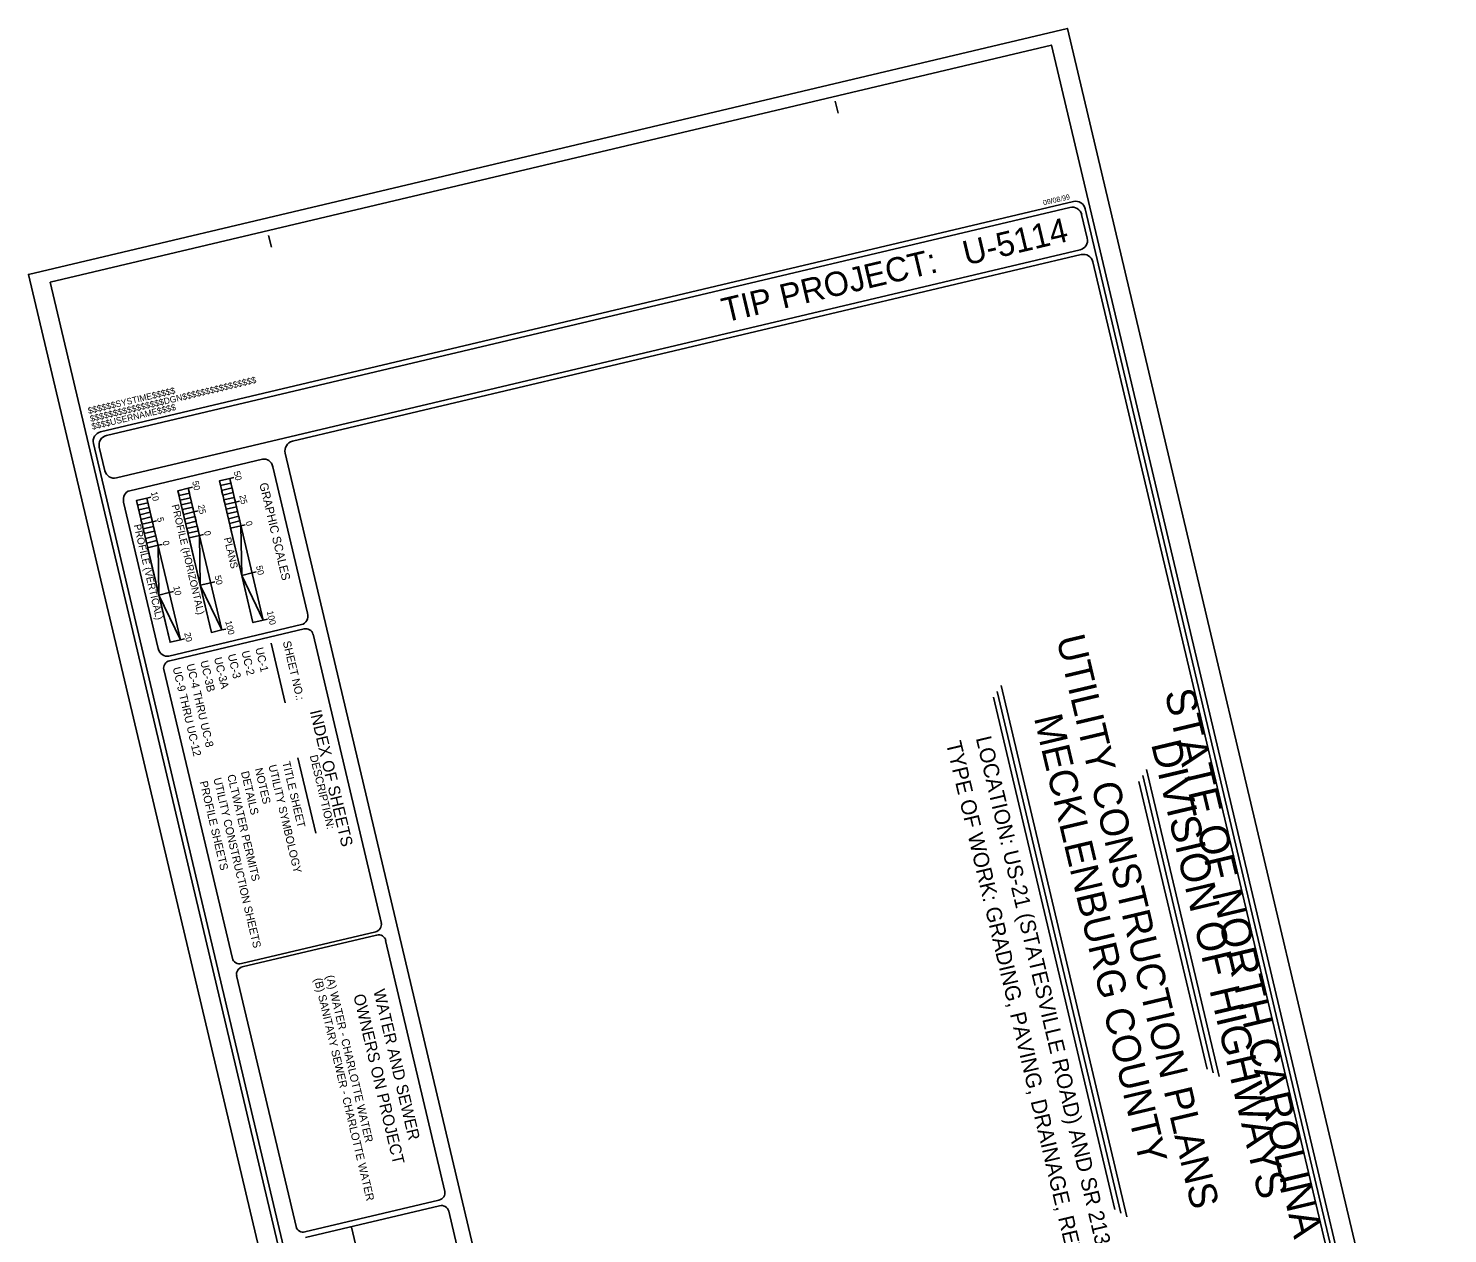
# Model space of a CAD drawing. Extents: x 1439200 to 1642353, y 394562 to 606444.
# Drawn here: x 1439200 to 1445633, y 600981 to 606444 of the extents above; entities that cross this region are included whole.
import ezdxf

# ---------------------------------------------------------------- set-up
doc = ezdxf.new("R2010")
doc.units = 0
doc.layers.add('Level 43', color=7, linetype='Continuous')
doc.layers.add('Water Line Text and Text Box and Leader Line (St)', color=7, linetype='Continuous')

msp = doc.modelspace()

# ---------------------------------------------------------------- linework, layer by layer
at = {"layer": 'Level 43'}
for p, q in [((1442857.6, 606113.3), (1442870.3, 606059.8)), ((1442857.6, 606113.3), (1442870.3, 606059.8)), ((1440288.6, 605505.1), (1440301.3, 605451.6)), ((1440288.6, 605505.1), (1440301.3, 605451.6)), ((1439599.3, 604406), (1443966.6, 605439.8)), ((1440396.5, 604572.1), (1443971.7, 605418.4)), ((1439484.4, 604604.9), (1439484.4, 604604.9)), ((1439484.4, 604604.9), (1439484.4, 604604.9)), ((1439484.4, 604604.9), (1439484.4, 604604.9)), ((1439484.4, 604604.9), (1439484.4, 604604.9)), ((1440363.8, 604519.2), (1441803.1, 598439.2)), ((1439659.1, 604348.4), (1440260.6, 604490.8)), ((1440308.3, 604456.9), (1440465.4, 603793.2)), ((1440112.9, 604403.8), (1440065.9, 604392.7)), ((1440065.9, 604392.7), (1440217.9, 603750.4)), ((1440112.9, 604403.8), (1440131.6, 604408.3)), ((1440112.9, 604403.8), (1440112.9, 604403.8)), ((1440264.9, 603761.6), (1440112.9, 604403.8)), ((1440131.6, 604408.3), (1440131.6, 604408.3)), ((1439736.9, 604314.8), (1439689.9, 604303.7)), ((1439689.9, 604303.7), (1439842, 603661.4)), ((1439736.9, 604314.8), (1439755.7, 604319.3)), ((1439736.9, 604314.8), (1439755.7, 604319.3)), ((1439736.9, 604314.8), (1439755.7, 604319.3)), ((1439736.9, 604314.8), (1439736.9, 604314.8)), ((1439889, 603672.6), (1439736.9, 604314.8)), ((1439736.9, 604314.8), (1439736.9, 604314.8)), ((1439889, 603672.6), (1439736.9, 604314.8)), ((1439736.9, 604314.8), (1439736.9, 604314.8)), ((1439889, 603672.6), (1439736.9, 604314.8)), ((1439755.7, 604319.3), (1439755.7, 604319.3)), ((1439924.8, 604359.3), (1439877.9, 604348.2)), ((1439877.9, 604348.2), (1440029.9, 603705.9)), ((1439924.8, 604359.3), (1439943.7, 604363.8)), ((1439924.8, 604359.3), (1439943.7, 604363.8)), ((1439924.8, 604359.3), (1439924.8, 604359.3)), ((1440076.9, 603717.1), (1439924.8, 604359.3)), ((1439924.8, 604359.3), (1439924.8, 604359.3)), ((1440076.9, 603717.1), (1439924.8, 604359.3)), ((1439943.7, 604363.8), (1439943.7, 604363.8)), ((1439950.2, 604252.2), (1439969, 604256.7)), ((1439950.2, 604252.2), (1439969, 604256.7)), ((1440148.3, 604254), (1440101.3, 604242.8)), ((1440138.2, 604296.8), (1440157, 604301.2)), ((1439762.3, 604207.8), (1439781, 604212.2)), ((1439762.3, 604207.8), (1439781, 604212.2)), ((1439762.3, 604207.8), (1439781, 604212.2)), ((1439960.3, 604209.5), (1439913.4, 604198.4)), ((1440163.5, 604189.7), (1440182.3, 604194.2)), ((1439772.4, 604165), (1439725.4, 604153.8)), ((1439975.6, 604145.2), (1439994.3, 604149.7)), ((1439975.6, 604145.2), (1439994.3, 604149.7)), ((1439787.6, 604100.8), (1439806.4, 604105.1)), ((1439787.6, 604100.8), (1439806.4, 604105.1)), ((1439787.6, 604100.8), (1439806.4, 604105.1)), ((1440214.2, 603975.6), (1440233, 603980.1)), ((1440026.3, 603931.2), (1439979.3, 603920)), ((1440026.3, 603931.2), (1440045.1, 603935.6)), ((1440026.3, 603931.2), (1440045.1, 603935.6)), ((1440214.2, 603975.6), (1440167.2, 603964.5)), ((1439838.2, 603886.6), (1439791.3, 603875.5)), ((1439838.2, 603886.6), (1439857.1, 603891.1)), ((1439838.2, 603886.6), (1439857.1, 603891.1)), ((1439838.2, 603886.6), (1439857.1, 603891.1)), ((1440438, 603741.5), (1439836.4, 603599.1)), ((1440217.9, 603750.4), (1440264.9, 603761.6)), ((1440264.9, 603761.6), (1440283.7, 603766)), ((1439841.1, 603577.7), (1440449.5, 603722.3)), ((1439842, 603661.4), (1439889, 603672.6)), ((1439889, 603672.6), (1439907.7, 603677)), ((1439889, 603672.6), (1439907.7, 603677)), ((1439889, 603672.6), (1439907.7, 603677)), ((1440029.9, 603705.9), (1440076.9, 603717.1)), ((1440076.9, 603717.1), (1440095.7, 603721.5)), ((1440076.9, 603717.1), (1440095.7, 603721.5)), ((1440490.9, 603698.3), (1440801.1, 602387.1)), ((1440299.9, 603657.1), (1440363.3, 603387.2)), ((1439814.6, 603537.9), (1440125.1, 602227.5)), ((1443608.6, 603465.9), (1444178.7, 601057.5)), ((1443608.6, 603465.9), (1444178.7, 601057.5)), ((1443575.1, 603411.8), (1444124.5, 601090.9)), ((1443591.8, 603438.8), (1444151.6, 601074.2)), ((1440421.6, 603137.2), (1440502.7, 602795.8)), ((1444267.4, 603085), (1444596.9, 601693.4)), ((1444234, 603030.8), (1444542.7, 601726.8)), ((1444250.7, 603057.9), (1444569.8, 601710.1)), ((1440166.1, 602205.3), (1440774.2, 602349)), ((1440169.7, 602190.5), (1440777.9, 602334.3)), ((1440819.3, 602310.4), (1441087.1, 601172.7)), ((1440143.4, 602150.7), (1440415.3, 601006.7)), ((1440453.7, 600989.4), (1441060.6, 601132.9)), ((1440456, 600964.1), (1441063.7, 601107.2)), ((1441105, 601083.4), (1441347.1, 600059.3)), ((1440664.9, 601010.8), (1440921.4, 599923.4))]:
    msp.add_line(p, q, dxfattribs=at)
for points in [[(1445632.9, 599164.9), (1443909.8, 606443.8), (1439200, 605328.8), (1440923.1, 598050)], [(1440112.9, 604403.8), (1440117.9, 604382.4), (1440070.9, 604371.3), (1440065.9, 604392.7)], [(1439736.9, 604314.8), (1439741.9, 604293.4), (1439695, 604282.3), (1439689.9, 604303.7)], [(1439924.8, 604359.3), (1439930, 604337.9), (1439883, 604326.8), (1439877.9, 604348.2)], [(1439935, 604316.5), (1439940.1, 604295.1), (1439893.1, 604283.9), (1439888, 604305.4)], [(1440123, 604361), (1440128, 604339.6), (1440081, 604328.5), (1440076, 604349.8)], [(1440133.1, 604318.2), (1440138.2, 604296.8), (1440091.2, 604285.7), (1440086.1, 604307.1)], [(1439747.1, 604272), (1439752.1, 604250.6), (1439705.1, 604239.5), (1439700.1, 604260.9)], [(1439945.2, 604273.7), (1439950.2, 604252.2), (1439903.2, 604241.2), (1439898.1, 604262.6)], [(1440143.2, 604275.4), (1440148.3, 604254), (1440101.3, 604242.8), (1440096.3, 604264.3)], [(1439757.2, 604229.2), (1439762.3, 604207.8), (1439715.2, 604196.7), (1439710.2, 604218.1)], [(1439767.3, 604186.3), (1439772.4, 604165), (1439725.4, 604153.8), (1439720.3, 604175.3)], [(1439955.3, 604230.9), (1439960.3, 604209.5), (1439913.4, 604198.4), (1439908.3, 604219.8)], [(1439965.4, 604188.1), (1439970.5, 604166.7), (1439923.5, 604155.5), (1439918.4, 604176.9)], [(1440153.4, 604232.6), (1440158.5, 604211.2), (1440111.4, 604200), (1440106.4, 604221.4)], [(1440163.5, 604189.7), (1440167.2, 603964.5), (1440116.5, 604178.6)], [(1439777.4, 604143.6), (1439782.5, 604122.2), (1439735.5, 604111), (1439730.5, 604132.4)], [(1439975.6, 604145.2), (1439979.3, 603920), (1439928.5, 604134.1)], [(1439787.6, 604100.8), (1439791.3, 603875.5), (1439740.6, 604089.6)], [(1440076.9, 603717.1), (1439979.3, 603920), (1440029.9, 603705.9)], [(1440264.9, 603761.6), (1440167.2, 603964.5), (1440217.9, 603750.4)], [(1439889, 603672.6), (1439791.3, 603875.5), (1439842, 603661.4)]]:
    msp.add_lwpolyline(points, close=True, dxfattribs=at)
for points in [[(1443937.4, 605659), (1439527.2, 604615)], [(1443937.4, 605659), (1439527.2, 604615)], [(1443921, 605632.5), (1439553.7, 604598.7)], [(1443999.3, 605492.8), (1443974, 605599.8)], [(1445490.4, 599289.4), (1443990.3, 605626.4)], [(1445463.9, 599305.8), (1444024.6, 605385.7)], [(1439494.5, 604562.1), (1440994.6, 598225.2)], [(1439521, 604545.8), (1439546.4, 604438.7)], [(1439631.6, 604296.7), (1439788.8, 603633)]]:
    msp.add_lwpolyline(points, dxfattribs=at)
for centre, start, end in [((1443947.7, 605616.2), 13.31805, 103.31805), ((1443931.4, 605589.7), 13.31805, 103.31805), ((1443956.7, 605482.7), 283.31805, 13.31805), ((1443982, 605375.6), 13.31805, 103.31805), ((1439537.6, 604572.2), 103.31805, 193.31805), ((1439564.1, 604555.9), 103.31805, 193.31805), ((1440406.8, 604529.3), 103.31805, 193.31805), ((1439589.4, 604448.9), 193.31805, 283.31805)]:
    msp.add_arc(centre, 44, start, end, dxfattribs=at)
for centre, major_axis, ratio, start_param, end_param in [((1440270.9, 604448), (-10.1, 42.8), 0.877963, 4.712389, 6.283185), ((1439669.4, 604305.6), (-10.1, 42.8), 0.877963, 0, 1.570796), ((1440428, 603784.3), (-10.1, 42.8), 0.877963, 3.141593, 4.712389), ((1440456.1, 603690.2), (33.8, 8), 0.941469, 6.283016, 7.853558), ((1439826.5, 603641.9), (10.1, -42.8), 0.877963, 4.712389, 6.283185), ((1439847.6, 603545.6), (33.8, 8), 0.941469, 1.570372, 3.141423), ((1440765.6, 602380.7), (-33.8, -8), 0.941469, 1.570196, 3.141423), ((1440786.3, 602302.2), (33.8, 8), 0.941469, 6.282374, 7.853553), ((1440158.6, 602237), (-33.8, -8), 0.941469, 6.283016, 7.853382), ((1440178, 602158.4), (33.8, 8), 0.941469, 1.570368, 3.141507), ((1441053.3, 601164.7), (33.8, 8), 0.941469, 4.711685, 6.282346), ((1441071.2, 601075.4), (33.8, 8), 0.941469, 6.283006, 7.853383), ((1440446.9, 601020.8), (-33.8, -8), 0.941469, 6.283015, 7.853382)]:
    msp.add_ellipse(centre, major_axis=major_axis, ratio=ratio, start_param=start_param, end_param=end_param, dxfattribs=at)
at = {"layer": 'Water Line Text and Text Box and Leader Line (St)'}
msp.add_lwpolyline([(1439298.8, 605293.4), (1440988.4, 598155.9), (1445527, 599230.3), (1443837.3, 606367.8)], close=True, dxfattribs=at)

# ---------------------------------------------------------------- texts
at = {"layer": 'Level 43'}
for s, height, rotation, p in [('09/08/99', 23.1, 13.31805, (1443801.9, 605641.6)), ('U-5114', 110, 13.31805, (1443450.1, 605369.1)), ('TIP PROJECT:', 110, 13.31805, (1442357.7, 605110.5)), ('$$$$$$SYSTIME$$$$$', 28.875, 13.31805, (1439473.1, 604695.9)), ('$$$$$$$$$$$$$$$$DGN$$$$$$$$$$$$$$$$', 28.875, 13.31805, (1439482.8, 604659.7)), ('$$$$USERNAME$$$$', 28.875, 13.31805, (1439490.4, 604624.4)), ('50', 28.97, 283.31805, (1440130.1, 604433.8)), ('50', 28.97, 283.31805, (1439942.2, 604389.3)), ('GRAPHIC SCALES', 38.63, 283.31805, (1440246.4, 604379.8)), ('10', 28.97, 283.31805, (1439755.2, 604340.9)), ('25', 28.97, 283.31805, (1440155.6, 604326.2)), ('PROFILE (HORIZONTAL)', 32.836, 283.31805, (1439849.2, 604282.4)), ('25', 28.97, 283.31805, (1439967.7, 604281.7)), ('PROFILE (VERTICAL)', 32.836, 283.31805, (1439676.9, 604192.3)), ('5', 29, 283.31805, (1439782.7, 604224.5)), ('0', 29, 283.31805, (1440183.8, 604207)), ('0', 29, 283.31805, (1439807.4, 604117.9)), ('0', 29, 283.31805, (1439807.4, 604117.9)), ('0', 29, 283.31805, (1439807.9, 604118)), ('0', 29, 283.31805, (1439995.3, 604162.4)), ('0', 29, 283.31805, (1439995.9, 604162.5)), ('PLANS', 32.84, 283.31805, (1440085.6, 604132.9)), ('50', 28.97, 283.31805, (1440231.5, 604005.6)), ('50', 28.97, 283.31805, (1440043.6, 603961.1)), ('10', 28.97, 283.31805, (1439856.5, 603912.8)), ('100', 28.97, 283.31805, (1440280.1, 603800.4)), ('100', 28.97, 283.31805, (1440092.2, 603755.8)), ('20', 28.97, 283.31805, (1439906.2, 603702.5)), ('SHEET NO.:', 36.26, 283.30383, (1440352.9, 603663)), ('UTILITY CONSTRUCTION PLANS ', 127.74, 283.34656, (1443859, 603679.7)), ('UC-3', 36.26, 283.30383, (1440103.3, 603604)), ('UC-2', 36.26, 283.30383, (1440165.7, 603618.7)), ('UC-1', 36.26, 283.30383, (1440228.1, 603633.5)), ('UC-9 THRU UC-12', 36.261, 283.30383, (1439853.8, 603545)), ('UC-4 THRU UC-8', 36.261, 283.30383, (1439916.2, 603559.7)), ('UC-3B', 36.26, 283.30383, (1439978.6, 603574.5)), ('UC-3A', 36.26, 283.30383, (1440041, 603589.2)), ('STATE OF NORTH CAROLINA', 135.18, 283.34656, (1444349.2, 603434.4)), ('INDEX OF SHEETS', 52.707, 283.30383, (1440475.1, 603348.3)), ('MECKLENBURG COUNTY ', 127.74, 283.34656, (1443757.2, 603319.5)), ('TYPE OF WORK: GRADING, PAVING, DRAINAGE, RETAINING WALLS & SIGNALS', 70.155, 283.30383, (1443358.5, 603204.5)), ('LOCATION: US-21 (STATESVILLE ROAD) AND SR 2136 (GILEAD ROAD)', 70.155, 283.30383, (1443493.9, 603227)), ('DIVISION OF HIGHWAYS', 135.18, 283.34656, (1444288.1, 603201.2)), ('DESCRIPTION:', 36.261, 283.30383, (1440475.1, 603146.5)), ('NOTES', 36.26, 283.30383, (1440225.6, 603087.5)), ('UTILITY SYMBOLOGY', 36.261, 283.30383, (1440288, 603102.3)), ('TITLE SHEET', 36.261, 283.30383, (1440350.4, 603117)), ('PROFILE SHEETS', 36.261, 283.30383, (1439976.1, 603028.5)), ('UTILITY CONSTRUCTION SHEETS', 36.261, 283.30383, (1440038.4, 603043.3)), ('CLTWATER PERMITS', 36.261, 283.30383, (1440100.8, 603058)), ('DETAILS', 36.26, 283.30383, (1440163.2, 603072.8)), ('(B) SANITARY SEWER - CHARLOTTE WATER', 36.261, 283.30383, (1440494.8, 602135.7)), ('(A) WATER - CHARLOTTE WATER', 36.261, 283.30383, (1440548.9, 602148.5)), ('OWNERS ON PROJECT ', 52.707, 283.30383, (1440672.6, 602060.8)), ('WATER AND SEWER', 52.707, 283.30383, (1440763.3, 602082.2))]:
    msp.add_text(s, height=height, rotation=rotation, dxfattribs=at).set_placement(p)

doc.saveas('drawing.dxf')
